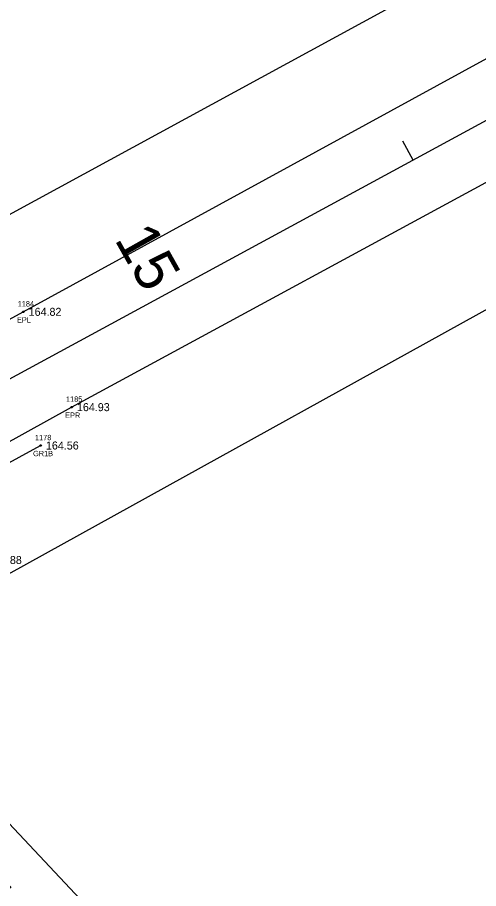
# Model space of a CAD drawing. Extents: x 2279339 to 2281902, y 1061267 to 1062892.
# Drawn here: x 2280304.9 to 2280391.4, y 1061741.1 to 1061904.3 of the extents above; entities that cross this region are included whole.
import ezdxf

# ---------------------------------------------------------------- set-up
doc = ezdxf.new("R2010")
doc.units = 0
for name, color, linetype in [('RD_EX_GuardRail', 7, 'Continuous'), ('RD_EX_GuardRail_txCode', 7, 'Continuous'), ('RD_EX_H2O', 7, 'Continuous'), ('RD_EX_Road', 7, 'Continuous'), ('RD_EX_Road_txCode', 7, 'Continuous'), ('RD_EX_TX_GuardRail_ELEV', 7, 'Continuous'), ('RD_EX_TX_Road_ELEV', 7, 'Continuous'), ('RD_EX_TX_UT_ELEV', 7, 'Continuous'), ('RD_EX_VEG', 7, 'Continuous'), ('RD_HC_Cl', 7, 'Continuous'), ('RD_HC_Data', 7, 'Continuous'), ('RD_HC_Data_Tic', 7, 'Continuous'), ('RD_HC_TX_Sta50', 7, 'Continuous'), ('RD_SMD_Locator', 7, 'Continuous')]:
    doc.layers.add(name, color=color, linetype=linetype)

msp = doc.modelspace()

# ---------------------------------------------------------------- linework, layer by layer
at = {"layer": 'RD_EX_GuardRail'}
msp.add_line((2280174.08, 1061751.56), (2280309.28, 1061824.13), dxfattribs=at)
at = {"layer": 'RD_EX_H2O'}
msp.add_lwpolyline([(2280269.9, 1061794.49), (2280270.02, 1061790.74), (2280293.77, 1061763.48), (2280320.49, 1061735.05), (2280335.4, 1061680.01), (2280309.48, 1061674.63), (2280300.03, 1061660.41), (2280304.47, 1061633.12), (2280315.65, 1061587.64), (2280305.89, 1061543.57), (2280270.77, 1061524.54), (2280257.61, 1061536.28), (2280249.22, 1061535.26), (2280269.33, 1061502.83), (2280301.34, 1061480.02), (2280355.94, 1061475.37), (2280377.91, 1061459.94), (2280379.03, 1061433), (2280360.13, 1061417.18), (2280333.79, 1061387.95)], dxfattribs=at)
at = {"layer": 'RD_EX_Road'}
for points in [[(2279554.31, 1061441.46), (2279636.61, 1061486.51), (2279673.46, 1061506.76), (2279683.06, 1061512.21), (2279723.14, 1061533.54), (2279809.28, 1061580.29), (2279896.91, 1061627.91), (2279977.07, 1061671.02), (2280059.64, 1061715.57), (2280142.91, 1061760.72), (2280228.83, 1061807.06), (2280306.04, 1061849.18), (2280392.98, 1061896.71), (2280482.82, 1061945.75), (2280567.83, 1061991.78), (2280649.94, 1062036.55), (2280660.56, 1062042.19), (2280676.12, 1062050.66), (2280737.28, 1062083.64), (2280828.54, 1062132.77), (2280887.86, 1062164.61), (2280934.91, 1062190.9)], [(2279906, 1061609.76), (2279987.33, 1061653.65), (2280069.09, 1061697.76), (2280153.19, 1061743.35), (2280194.51, 1061765.35), (2280202.82, 1061771.34), (2280211.47, 1061775.32), (2280215.93, 1061780.7), (2280225.22, 1061785.77), (2280231.78, 1061787.38), (2280251.88, 1061797.82), (2280255.66, 1061801.36), (2280256.83, 1061804.75), (2280266.2, 1061806.83), (2280270.78, 1061807.29), (2280284.33, 1061814.31), (2280315.09, 1061831.32), (2280403.05, 1061879.04)]]:
    msp.add_lwpolyline(points, dxfattribs=at)
at = {"layer": 'RD_EX_VEG'}
for points in [[(2279558.89, 1061483.89), (2279567.79, 1061465.98), (2279895.37, 1061645.37), (2280383.77, 1061911.19), (2280927.05, 1062203.11)], [(2279742.03, 1061456.73), (2279738.34, 1061498.5), (2279914.03, 1061591.25), (2280293.74, 1061794.82), (2280950.97, 1062158.54)]]:
    msp.add_lwpolyline(points, dxfattribs=at)
at = {"layer": 'RD_HC_Cl'}
msp.add_line((2279559.77, 1061433.17), (2280939.55, 1062181.67), dxfattribs=at)
at = {"layer": 'RD_HC_Data_Tic'}
msp.add_line((2280379.08, 1061877.62), (2280377.17, 1061881.14), dxfattribs=at)
at = {"layer": 'RD_SMD_Locator'}
for centre in [(2280306.04, 1061849.18), (2280315.09, 1061831.32), (2280309.28, 1061824.13)]:
    msp.add_circle(centre, 0.15, dxfattribs=at)

# ---------------------------------------------------------------- texts
at = {"layer": 'RD_EX_GuardRail_txCode'}
for s, p in [('1178', (2280308.22, 1061825.13)), ('GR1B', (2280307.86, 1061822.13))]:
    msp.add_text(s, height=1, dxfattribs=at).set_placement(p)
at = {"layer": 'RD_EX_Road_txCode'}
for s, p in [('1184', (2280304.98, 1061850.18)), ('EPL', (2280304.84, 1061847.18)), ('1185', (2280314.03, 1061832.32)), ('EPR', (2280313.87, 1061829.32))]:
    msp.add_text(s, height=1, dxfattribs=at).set_placement(p)
at = {"layer": 'RD_EX_TX_GuardRail_ELEV'}
msp.add_text('164.56', height=1.5, dxfattribs=at).set_placement((2280310.28, 1061823.38))
at = {"layer": 'RD_EX_TX_Road_ELEV'}
for s, p in [('164.82', (2280307.04, 1061848.43)), ('164.93', (2280316.09, 1061830.57))]:
    msp.add_text(s, height=1.5, dxfattribs=at).set_placement(p)
at = {"layer": 'RD_EX_TX_UT_ELEV'}
msp.add_text('162.88', height=1.5, dxfattribs=at).set_placement((2280299.62, 1061801.93))
at = {"layer": 'RD_HC_Data'}
msp.add_text('S 44%%d 52\' 11" E', height=6, rotation=314.8698, dxfattribs=at).set_placement((2280273.26, 1061763.6))
at = {"layer": 'RD_HC_TX_Sta50'}
msp.add_text('15', height=8, rotation=299.3657, dxfattribs=at).set_placement((2280323.02, 1061862.78))

doc.saveas('drawing.dxf')
